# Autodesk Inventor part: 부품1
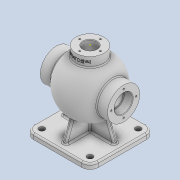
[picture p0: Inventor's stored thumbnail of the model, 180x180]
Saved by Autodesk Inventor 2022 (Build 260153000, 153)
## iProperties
Created: 2024-04
Part Number: 부품1
Material: 일반
Document SubType Name: Modeling
Designer: Admin
Density: 1 g/cm^3
Appearance: 기본값
Author: Admin
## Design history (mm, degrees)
sketch "스케치2"
  geometry: L1 (-403.888, 0)-(403.888, 0) reference; L2 (0, -37.2)-(0, 69.2) reference; L3 (-288.492, 0)-(288.492, 0); C1 r 22 at (0, 0); A1 r 54 centre (0, 0) between (54, 0) and (-54, 0); 3 further points
  constraints: 2 centre point, 2 coincident, 2 end point, 2 point on circle, 2 point on line, 1 horizontal, 1 midpoint
  dimensions: "d6" = 54 radius of A1; "d16" = 44 diameter of C1
revolve "회전1" sketch "스케치2" stored, may be unused: angle "d7" = 90 deg
node "작업 평면1"
sketch "스케치3"
  geometry: C1 r 27 at (0, 0); 1 further point
  constraints: 1 centre point, 1 coincident
  dimensions: "d9" = 54 diameter of C1
extrude "돌출1" join sketch "스케치3" stored distance "d10" = 16; taper "d11" = 0 deg
node "작업 평면2"
sketch "스케치4"
  geometry: L1 (-43.4, 0)-(43.4, 0) reference; L2 (0, -43.4)-(0, 43.4) reference; C1 r 31 at (0, 0); 1 further point
  constraints: 1 centre point, 1 coincident
  dimensions: "d13" = 62 diameter of C1
extrude "돌출2" join sketch "스케치4" stored distance "d14" = 10; taper "d15" = 0 deg
sketch "스케치5"
  geometry: L1 (-58.813, 0)-(58.813, 0); A1 r 44 centre (0, 0) between (44, 0) and (-44, 0); 2 further points
  constraints: 2 coincident, 2 end point, 2 point on circle, 2 point on line, 1 centre point, 1 horizontal, 1 midpoint
  dimensions: "d18" = 44 radius of A1
revolve "회전2" sketch "스케치5" stored, may be unused: angle "d19" = 90 deg
sketch "스케치6"
  geometry: L1 (-97.524, 0)-(97.524, 0); L2 (-65, -31)-(-65, 31) reference; L3 (-65, 17.5)-(-49, 17.5); L4 (-49, 17.5)-(-49, 0); L5 (-49, 0)-(-65, 0); L6 (-65, 0)-(-65, 17.5); L7 (-49, 15)-(-39, 15); L8 (-39, 15)-(-39, 0); L9 (-39, 0)-(-49, 0); L10 (-49, 0)-(-49, 15); L11 (0, -77.8)-(0, 88.8) reference; L12 (65, 17.5)-(49, 17.5); L13 (65, 0)-(65, 17.5); L14 (49, 0)-(65, 0); L15 (49, 0)-(49, 15); L16 (49, 15)-(39, 15); L17 (49, 17.5)-(49, 0); L18 (39, 15)-(39, 0); L19 (39, 0)-(49, 0); C1 r 44 at (0, 0) reference; 7 further points
  constraints: 34 end point, 8 symmetric about line, 5 point on line, 4 parallel, 3 horizontal, 2 perpendicular, 1 coincident, 1 midpoint, 1 other
  dimensions: "d20" = 35 diameter of L3 L1; "d21" = 30 diameter of L7 L1; "d22" = 16 distance between parallel lines of L4 L2; "d23" = 10 distance between parallel lines of L4 L8
revolve "회전3" sketch "스케치6" stored, may be unused: angle "d24" = 90 deg
sketch "스케치7"
  geometry: 1 further point
sketch "스케치8"
  geometry: 1 further point
sketch "스케치9"
  geometry: C1 r 13 at (0, 0); 1 further point
  constraints: 1 centre point, 1 coincident
  dimensions: "d25" = 26 diameter of C1
extrude "돌출3" cut sketch "스케치9" stored distance "d26" = 10; taper "d27" = 0 deg
node "작업 평면3"
sketch "스케치10"
  geometry: L1 (-62.5, 62.5)-(62.5, 62.5); L2 (62.5, 62.5)-(62.5, -62.5); L3 (62.5, -62.5)-(-62.5, -62.5); L4 (-62.5, -62.5)-(-62.5, 62.5); L5 (-62.5, 62.5)-(62.5, -62.5); L6 (62.5, 62.5)-(-62.5, -62.5); 1 further point
  constraints: 12 end point, 2 midpoint, 2 parallel, 1 horizontal, 1 perpendicular
  dimensions: "d29" = 125 distance of L2.end L3.end; "d30" = 125 distance of L1.end L2.end
extrude "돌출4" join sketch "스케치10" distance "d31" = 10; taper "d32" = 0 deg
sketch "스케치11"
  geometry: L1 (46.765, 27)-(65, 27) reference; L2 (65, 27)-(65, 13) reference; L3 (65, 13)-(42.036, 13) reference; L4 (42.036, -13)-(65, -13) reference; L5 (65, -13)-(65, -27) reference; L6 (65, -27)-(46.765, -27) reference; L7 (-85, 62.5)-(-75, 62.5) reference; L8 (-75, 62.5)-(-75, -62.5) reference; L9 (-75, -62.5)-(-85, -62.5) reference; L10 (-85, -62.5)-(-85, 62.5) reference; L11 (-38.966, -37.385)-(-75, -50.5); L12 (-115, 0)-(95, 0) reference; L13 (-38.966, 37.385)-(-75, 50.5); L14 (-75, -50.5)-(-75, 50.5); L15 (-75, 62.5)-(-75, -62.5) reference; A1 r 54 centre (0, 0) between (46.765, 27) and (0, 54) reference; A2 r 54 centre (0, 0) between (0, 54) and (0, -54) reference; A3 r 44 centre (0, 0) between (42.036, 13) and (0, 44) reference; A4 r 44 centre (0, 0) between (0, 44) and (0, -44) reference; A5 r 44 centre (0, 0) between (0, -44) and (42.036, -13) reference; A6 r 54 centre (0, 0) between (0, -54) and (46.765, -27) reference; A7 r 54 centre (0, 0) between (54, 0) and (-38.966, -37.385); A8 r 54 centre (0, 0) between (-38.966, 37.385) and (54, 0); 2 further points
  constraints: 6 end point, 6 point on circle, 2 centre point, 2 point on line, 2 symmetric about line, 1 coincident, 1 collinear, 1 other
  dimensions: "d33" = 20 deg angle of L9 L11; "d34" = 12 distance from line of L11.end L9
extrude "돌출5" join sketch "스케치11" stored distance "d35" = 8; taper "d36" = 0 deg
sketch "스케치15"
  geometry: L1 (44.215, 31)-(65, 31) reference; L2 (65, 31)-(65, 17.5) reference; L3 (65, 17.5)-(49, 17.5) reference; L4 (49, 17.5)-(49, 15) reference; L5 (49, 15)-(41.364, 15) reference; L6 (13, 42.036)-(13, 65) reference; L7 (13, 65)-(27, 65) reference; L8 (27, 65)-(27, 46.765) reference; L9 (-65, 31)-(-44.215, 31) reference; L10 (-27, 46.765)-(-27, 65) reference; L11 (-27, 65)-(-13, 65) reference; L12 (-13, 65)-(-13, 42.036) reference; L13 (-41.364, 15)-(-49, 15) reference; L14 (-49, 15)-(-49, 17.5) reference; L15 (-49, 17.5)-(-65, 17.5) reference; L16 (-65, 17.5)-(-65, 31) reference; L17 (-44.215, -31)-(-65, -31) reference; L18 (-65, -31)-(-65, -17.5) reference; L19 (-65, -17.5)-(-49, -17.5) reference; L20 (-49, -17.5)-(-49, -15) reference; L21 (-49, -15)-(-41.364, -15) reference; L22 (41.364, -15)-(49, -15) reference; L23 (49, -15)-(49, -17.5) reference; L24 (49, -17.5)-(65, -17.5) reference; L25 (65, -17.5)-(65, -31) reference; L26 (65, -31)-(44.215, -31) reference; L27 (-4, -54)-(0, -54) reference; L28 (-4, -75)-(-4, -54) reference; L29 (-62.5, -75)-(-4, -75) reference; L30 (-62.5, -85)-(-62.5, -75) reference; L31 (62.5, -85)-(-62.5, -85) reference; L32 (62.5, -75)-(62.5, -85) reference; L33 (4, -75)-(62.5, -75) reference; L34 (4, -54)-(4, -75) reference; L35 (0, -54)-(4, -54) reference; L36 (35.644, -34.183)-(50.5, -75); L37 (50.5, -75)-(0, -75); L38 (0, -75)-(0, -49.386); A1 r 44 centre (0, 0) between (41.364, 15) and (13, 42.036) reference; A2 r 54 centre (0, 0) between (44.215, 31) and (27, 46.765) reference; A3 r 54 centre (0, 0) between (-27, 46.765) and (-44.215, 31) reference; A4 r 44 centre (0, 0) between (-13, 42.036) and (-41.364, 15) reference; A5 r 44 centre (0, 0) between (-41.364, -15) and (41.364, -15) reference; A6 r 54 centre (0, 0) between (-44.215, -31) and (0, -54) reference; A7 r 54 centre (0, 0) between (0, -54) and (44.215, -31) reference; A8 r 49.386 centre (0, 0) between (0, -49.386) and (35.644, -34.183); 3 further points
  constraints: 6 end point, 2 point on circle, 1 centre point, 1 coincident, 1 collinear, 1 horizontal, 1 perpendicular
  dimensions: "d40" = 20 deg angle of L32 L36; "d41" = 12 distance from line of L36.end L32
extrude "돌출6" join sketch "스케치15" stored distance "d42" = 8; taper "d43" = 0 deg
sketch "스케치16" dims "d44" = 48
  geometry: L1 (0, -115)-(0, 95) reference; L2 (87.5, 0)-(-87.5, 0) reference; 3 further points
  constraints: 2 vertical alignment, 1 coincident, 2 other
hole "구멍1" sketch "스케치16" at (0, 24) diameter "d45" = 3.242; stored, may be unused: countersink angle "d49" = 90 deg, drill point angle "d51" = 90 deg; dims "d46" = 12, "d47" = 4, "d48" = 2, "d50" = 15
sketch "스케치17" dims "d55" = 40
  geometry: 3 further points
  constraints: 2 vertical alignment, 1 coincident, 2 other
hole "구멍2" sketch "스케치17" at (0, -20) diameter "d56" = 3.242; stored, may be unused: countersink angle "d60" = 90 deg, drill point angle "d62" = 90 deg; dims "d57" = 9, "d58" = 4, "d59" = 2, "d61" = 11
sketch "스케치18"
  geometry: 1 further point
fillet "모깎기1" dims "d66" = 16
sketch "스케치19"
  geometry: C1 r 5.5 at (-46.5, -46.5); C2 r 5.5 at (-46.5, 46.5); C3 r 5.5 at (46.5, -46.5); C4 r 5.5 at (46.5, 46.5); A1 r 16 centre (-46.5, -46.5) between (-62.5, -46.5) and (-46.5, -62.5) reference; A2 r 16 centre (-46.5, 46.5) between (-46.5, 62.5) and (-62.5, 46.5) reference; A3 r 16 centre (46.5, -46.5) between (46.5, -62.5) and (62.5, -46.5) reference; A4 r 16 centre (46.5, 46.5) between (62.5, 46.5) and (46.5, 62.5) reference; 1 further point
  constraints: 4 centre point, 4 coincident
  dimensions: "d67" = 11 diameter of C1; "d68" = 11 diameter of C2; "d69" = 11 diameter of C3; "d70" = 11 diameter of C4
extrude "돌출7" cut sketch "스케치19" extent not by distance; stored distance "d71" = 0; taper "d72" = 0 deg
node "작업 평면4"
sketch "스케치20"
  geometry: L1 (-91, 0)-(91, 0) reference; L2 (0, -115)-(0, 95) reference; L3 (27, 65)-(-27, 65) reference; 2 further points
  constraints: 1 point on line, 1 other
  dimensions: "d74" = 9 distance from line of L3 point (0, 56)
feature "엠보싱1" sketch "스케치20" dims "d75" = 0.5, "d76" = 0
chamfer "모따기1" distance "d77" = 1; stored, may be unused: second distance "d78" = 2, angle "d79" = 45 deg
fillet "모깎기2" dims "d80" = 3
fillet "모깎기3" dims "d81" = 3
node "솔리드1"
mirror "미러1"
mirror "미러2"
pattern_circular "원형 패턴1" dims angle "d53" = 360 deg
mirror "미러3"
pattern_circular "원형 패턴2" dims angle "d64" = 360 deg
node "절단 모서리 투영1"
node "절단 모서리 투영3"
feature "A9D066F2-1C7D-4E18-AEED-F7BC21143FA4" dims "d45" = 3.242, "d46" = 12, "d47" = 4, "d48" = 2, "d49" = 90 deg, "d50" = 15, "d51" = 90 deg
other parameters: "d8" = 65, "d12" = -65, "d73" = 86.5
